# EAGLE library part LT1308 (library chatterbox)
Adjustable Output Low Voltage Boost Regulator with Detect
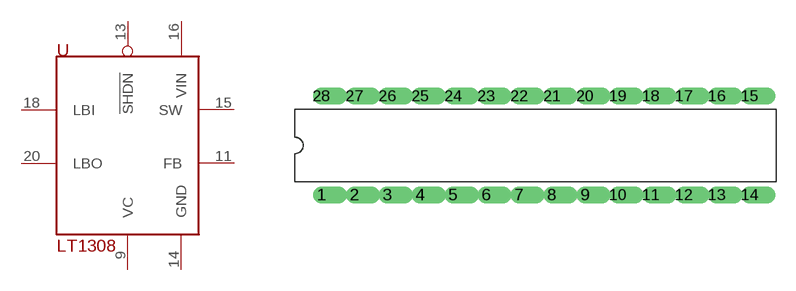
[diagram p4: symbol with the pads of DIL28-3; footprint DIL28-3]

Designator prefix -

## LT1308102  [DIL28-3]
9  VC  pwr
11  FB  pwr
13  !SHDN  pas
14  GND  pas
15  SW  pas
16  VIN  pas
18  LBI  pas
20  LBO  pwr

## Footprint DIL28-3 (pad centres in mm)
Dual In Line 28, 0.3 inch
drill 0.813 offset: 1 -16.51,-3.81; 2 -13.97,-3.81; 3 -11.43,-3.81; 4 -8.89,-3.81; 5 -6.35,-3.81; 6 -3.81,-3.81; 7 -1.27,-3.81; 8 1.27,-3.81; 9 3.81,-3.81; 10 6.35,-3.81; 11 8.89,-3.81; 12 11.43,-3.81; 13 13.97,-3.81; 14 16.51,-3.81; 15 16.51,3.81; 16 13.97,3.81; 17 11.43,3.81; 18 8.89,3.81; 19 6.35,3.81; 20 3.81,3.81; 21 1.27,3.81; 22 -1.27,3.81; 23 -3.81,3.81; 24 -6.35,3.81; 25 -8.89,3.81; 26 -11.43,3.81; 27 -13.97,3.81; 28 -16.51,3.81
